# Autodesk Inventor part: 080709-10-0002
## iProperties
Created: 2008-07
Part Number: 080709-10-0002
Document SubType Name: Modeling
Designer: WH
Density: 1 g/cm^3
Mass: 16.513 g
Surface Area: 35.9869 cm^2
Volume: 16.513 cm^3
Stock Number: 080709-10-0002
Author: WH
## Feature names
1. Extrusion1
